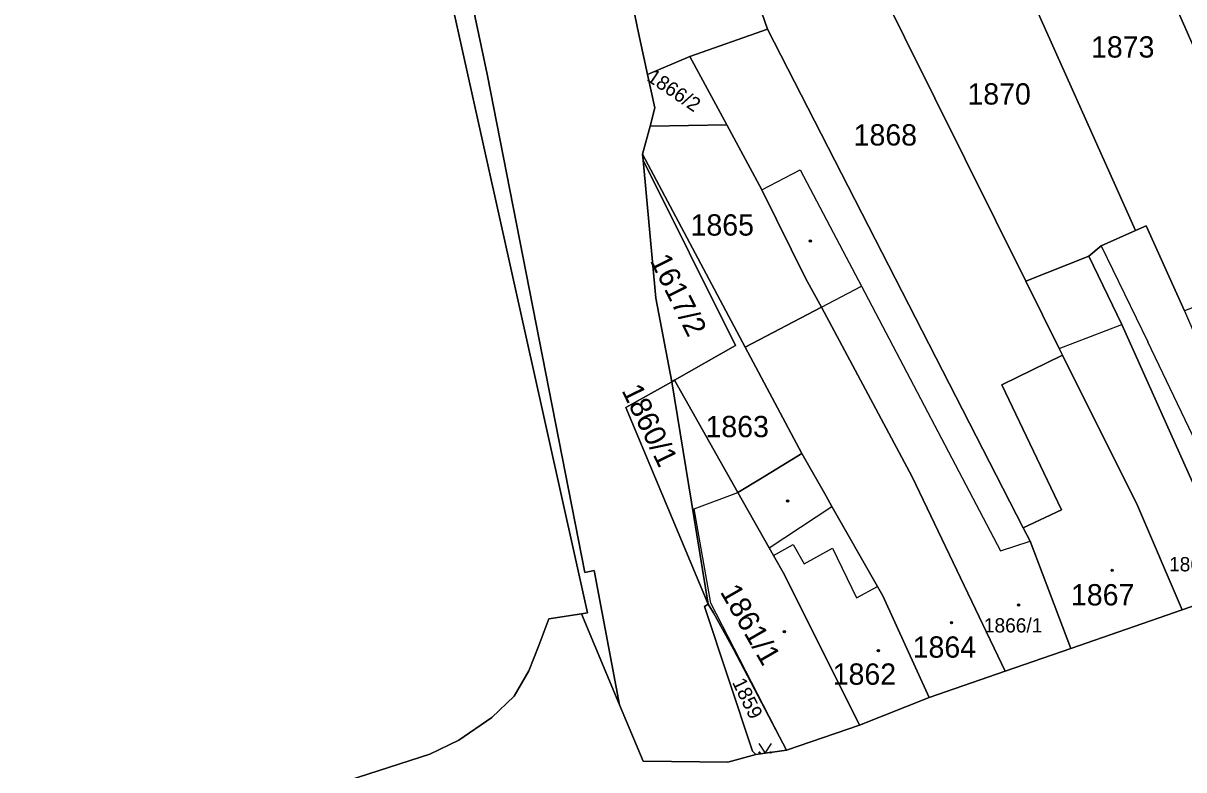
# Model space of a CAD drawing. Extents: x -596233 to -595156, y -1161235 to -1159375.
# Drawn here: x -595945.9 to -595853.3, y -1161150.2 to -1161090.6 of the extents above; entities that cross this region are included whole.
import ezdxf

# ---------------------------------------------------------------- set-up
doc = ezdxf.new("R2010")
doc.units = 0
for name, color, linetype in [('KN_CAR_KR', 7, 'Continuous'), ('KN_KULTURY', 7, 'Continuous'), ('KN_PARC_CIS_POZ', 7, 'Continuous'), ('KN_PARC_CIS_STAV', 7, 'Continuous'), ('KN_PARC_PLOCHA', 7, 'Continuous'), ('parcely_l', 7, 'Continuous')]:
    doc.layers.add(name, color=color, linetype=linetype)

msp = doc.modelspace()

# ---------------------------------------------------------------- linework, layer by layer
at = {"layer": 'KN_CAR_KR'}
for points in [[(-595886.97, -1161103.89), (-595883.91, -1161102.29)], [(-595883.91, -1161102.29), (-595880.24, -1161109.28)], [(-595859.88, -1161108.37), (-595856.16, -1161116.02)], [(-595880.24, -1161109.28), (-595879.02, -1161111.59)], [(-595882.21, -1161113.27), (-595879.02, -1161111.59)], [(-595879.02, -1161111.59), (-595867.93, -1161132.71)], [(-595863.23, -1161116.56), (-595858.25, -1161114.64)], [(-595851.12, -1161126.58), (-595856.16, -1161116.02)], [(-595892.35, -1161129.36), (-595888.87, -1161128.05)], [(-595891.04, -1161136.9), (-595892.35, -1161129.36)], [(-595886.37, -1161132.47), (-595881.37, -1161129.17)], [(-595886.03, -1161133.08), (-595884.47, -1161132.2)], [(-595884.47, -1161132.2), (-595883.59, -1161133.76)], [(-595883.59, -1161133.76), (-595881.33, -1161132.49)], [(-595881.33, -1161132.49), (-595879.4, -1161136.46)], [(-595867.93, -1161132.71), (-595865.56, -1161131.93)], [(-595879.4, -1161136.46), (-595877.74, -1161135.56)], [(-595884.99, -1161148.61), (-595891.04, -1161136.9)]]:
    msp.add_lwpolyline(points, dxfattribs=at)
at = {"layer": 'KN_KULTURY'}
msp.add_lwpolyline([(-595887.2018, -1161148.1016), (-595886.7018, -1161148.8516), (-595886.2018, -1161148.1016)], dxfattribs=at)
for centre, radius in [((-595883.1, -1161107.98), 0.09), ((-595883.1, -1161107.98), 0.0398), ((-595884.91, -1161128.73), 0.09), ((-595884.91, -1161128.73), 0.0398), ((-595859.01, -1161134.27), 0.09), ((-595859.01, -1161134.27), 0.0398), ((-595866.48, -1161137.03), 0.09), ((-595866.48, -1161137.03), 0.0398), ((-595885.16, -1161139.17), 0.09), ((-595885.16, -1161139.17), 0.0398), ((-595871.83, -1161138.45), 0.09), ((-595871.83, -1161138.45), 0.0398), ((-595877.66, -1161140.69), 0.09), ((-595877.66, -1161140.69), 0.0398), ((-595887.152, -1161148.8014), 0.05), ((-595886.2526, -1161148.8014), 0.05)]:
    msp.add_circle(centre, radius, dxfattribs=at)
at = {"layer": 'KN_PARC_PLOCHA'}
for points in [[(-595932.45, -1161008.33), (-595923.68, -1161035.97), (-595916.79, -1161060.49), (-595915.17, -1161066.86), (-595911.35, -1161082.95), (-595908.87, -1161094.65), (-595901.08, -1161134.44), (-595900.34, -1161134.29), (-595898.31, -1161145), (-595901.34, -1161137.73), (-595900.87, -1161137.65), (-595919, -1161056.06), (-595928.46, -1161024.22), (-595963.05, -1160926.68)], [(-595963.05, -1160926.68), (-595928.46, -1161024.22), (-595919, -1161056.06), (-595900.87, -1161137.65), (-595901.34, -1161137.73), (-595903.95, -1161138.15), (-595904.75, -1161140.26), (-595905.56, -1161142.28), (-595906.73, -1161144.3), (-595908.51, -1161146.01), (-595911.15, -1161147.82), (-595913.46, -1161148.94), (-595935.55, -1161156.06), (-595938.4, -1161156.98), (-595944.25, -1161155.13), (-595946.59, -1161152.37)], [(-595897.87, -1161086.16), (-595896.89, -1161090.99), (-595896.08, -1161094.7), (-595895.5, -1161097.34), (-595895.88, -1161098.81), (-595896.47, -1161101.05), (-595896.43, -1161101.54), (-595895.42, -1161112.55), (-595894.15, -1161119.21), (-595897.81, -1161121.28), (-595891.25, -1161136.97), (-595891.54, -1161137.15), (-595887.7, -1161148.71), (-595887.43, -1161148.97), (-595889.67, -1161149.57), (-595896.44, -1161149.51), (-595898.31, -1161145), (-595900.34, -1161134.29), (-595901.08, -1161134.44), (-595908.87, -1161094.65), (-595911.35, -1161082.95)], [(-595935.55, -1161156.06), (-595913.46, -1161148.94), (-595911.15, -1161147.82), (-595908.51, -1161146.01), (-595906.73, -1161144.3), (-595905.56, -1161142.28), (-595904.75, -1161140.26), (-595903.95, -1161138.15), (-595901.34, -1161137.73), (-595898.31, -1161145), (-595896.44, -1161149.51), (-595889.67, -1161149.57), (-595887.43, -1161148.97), (-595884.99, -1161148.61), (-595879.16, -1161146.62), (-595873.62, -1161144.41), (-595867.56, -1161142.31), (-595862.31, -1161140.5), (-595853.42, -1161137.42), (-595848.96, -1161135.89)]]:
    msp.add_lwpolyline(points, dxfattribs=at)
for points in [[(-595837.24, -1161088.2), (-595841.21, -1161090.03), (-595839.94, -1161093.17), (-595845.26, -1161095.8), (-595850.16, -1161097.83), (-595858.78, -1161078.24), (-595844.69, -1161072.03)], [(-595850.16, -1161097.83), (-595848.83, -1161100.85), (-595847.65, -1161103.46), (-595844.56, -1161110.24), (-595853.24, -1161113.55), (-595856.29, -1161106.76), (-595857.14, -1161107.14), (-595868.2, -1161082.4), (-595862.18, -1161079.61), (-595861.21, -1161079.27), (-595858.78, -1161078.24)], [(-595868.2, -1161082.4), (-595876.47, -1161086.05), (-595878, -1161086.81), (-595880.89, -1161088.44), (-595880.82, -1161089.01), (-595886.39, -1161089.71), (-595886.97, -1161089.77), (-595886.51, -1161091.06), (-595892.7, -1161093.24), (-595896.08, -1161094.7), (-595896.89, -1161090.99), (-595897.87, -1161086.16), (-595891.04, -1161084.75), (-595882.09, -1161083.33), (-595877.12, -1161082.53), (-595861.21, -1161079.27), (-595862.18, -1161079.61)], [(-595857.14, -1161107.14), (-595859.88, -1161108.37), (-595860.87, -1161109.2), (-595865.9, -1161111.18), (-595878, -1161086.81), (-595876.47, -1161086.05), (-595868.2, -1161082.4)], [(-595865.9, -1161111.18), (-595863.23, -1161116.56), (-595862.97, -1161117.08), (-595867.82, -1161119.46), (-595863.04, -1161129.43), (-595866.1, -1161130.88), (-595886.51, -1161091.06), (-595886.97, -1161089.77), (-595886.39, -1161089.71), (-595880.82, -1161089.01), (-595880.89, -1161088.44), (-595878, -1161086.81)], [(-595866.1, -1161130.88), (-595865.56, -1161131.93), (-595862.31, -1161140.5), (-595867.56, -1161142.31), (-595874.97, -1161126.8), (-595882.21, -1161113.27), (-595883.44, -1161110.99), (-595886.97, -1161103.89), (-595889.75, -1161098.72), (-595892.7, -1161093.24), (-595886.51, -1161091.06)], [(-595889.75, -1161098.72), (-595895.88, -1161098.81), (-595895.5, -1161097.34), (-595896.08, -1161094.7), (-595892.7, -1161093.24)], [(-595882.21, -1161113.27), (-595888.28, -1161116.45), (-595896.47, -1161101.05), (-595895.88, -1161098.81), (-595889.75, -1161098.72), (-595886.97, -1161103.89), (-595883.44, -1161110.99)], [(-595888.28, -1161116.45), (-595883.76, -1161124.94), (-595887.08, -1161126.96), (-595888.87, -1161128.05), (-595893.94, -1161119.09), (-595889.07, -1161116.33), (-595896.43, -1161101.54), (-595896.47, -1161101.05)], [(-595893.94, -1161119.09), (-595894.15, -1161119.21), (-595895.42, -1161112.55), (-595896.43, -1161101.54), (-595889.07, -1161116.33)], [(-595853.24, -1161113.55), (-595850.76, -1161119.29), (-595844.29, -1161134.3), (-595848.96, -1161135.89), (-595852.61, -1161127.22), (-595858.25, -1161114.64), (-595860.87, -1161109.2), (-595859.88, -1161108.37), (-595857.14, -1161107.14), (-595856.29, -1161106.76)], [(-595848.96, -1161135.89), (-595853.42, -1161137.42), (-595857, -1161129.1), (-595862.97, -1161117.08), (-595863.23, -1161116.56), (-595865.9, -1161111.18), (-595860.87, -1161109.2), (-595858.25, -1161114.64), (-595852.61, -1161127.22)], [(-595867.56, -1161142.31), (-595873.62, -1161144.41), (-595877.32, -1161136.3), (-595877.74, -1161135.56), (-595881.37, -1161129.17), (-595881.85, -1161128.29), (-595883.76, -1161124.94), (-595888.28, -1161116.45), (-595882.21, -1161113.27), (-595874.97, -1161126.8)], [(-595853.42, -1161137.42), (-595862.31, -1161140.5), (-595865.56, -1161131.93), (-595866.1, -1161130.88), (-595863.04, -1161129.43), (-595867.82, -1161119.46), (-595862.97, -1161117.08), (-595857, -1161129.1)], [(-595891.25, -1161136.97), (-595897.81, -1161121.28), (-595894.15, -1161119.21)], [(-595888.87, -1161128.05), (-595886.37, -1161132.47), (-595886.03, -1161133.08), (-595885.15, -1161134.64), (-595883.36, -1161138.21), (-595883.21, -1161138.52), (-595879.16, -1161146.62), (-595884.99, -1161148.61), (-595889.21, -1161140.56), (-595890.83, -1161137.66), (-595891.25, -1161136.97), (-595894.15, -1161119.21), (-595893.94, -1161119.09)], [(-595873.62, -1161144.41), (-595879.16, -1161146.62), (-595883.21, -1161138.52), (-595883.36, -1161138.21), (-595885.15, -1161134.64), (-595886.03, -1161133.08), (-595886.37, -1161132.47), (-595888.87, -1161128.05), (-595887.08, -1161126.96), (-595883.76, -1161124.94), (-595881.85, -1161128.29), (-595881.37, -1161129.17), (-595877.74, -1161135.56), (-595877.32, -1161136.3)], [(-595884.99, -1161148.61), (-595887.43, -1161148.97), (-595887.7, -1161148.71), (-595891.54, -1161137.15), (-595891.25, -1161136.97), (-595890.83, -1161137.66), (-595889.21, -1161140.56)]]:
    msp.add_lwpolyline(points, close=True, dxfattribs=at)
at = {"layer": 'parcely_l'}
for points in [[(-595970.85, -1160905.06), (-595963.05, -1160926.68), (-595928.46, -1161024.22), (-595919, -1161056.06), (-595900.87, -1161137.65), (-595901.34, -1161137.73)], [(-595898.31, -1161145), (-595900.34, -1161134.29), (-595901.08, -1161134.44), (-595908.87, -1161094.65), (-595911.35, -1161082.95), (-595915.17, -1161066.86), (-595916.79, -1161060.49), (-595923.68, -1161035.97), (-595932.45, -1161008.33), (-595931.85, -1161008.07), (-595933.08, -1161004.4), (-595933.76, -1161004.69), (-595934.5, -1161002.59), (-595933.82, -1161002.3), (-595934.86, -1160999.42), (-595935.6, -1160999.68), (-595936.32, -1160997.73), (-595935.57, -1160997.47), (-595936.57, -1160994.57), (-595937.32, -1160994.82), (-595945.84, -1160970.67), (-595945.16, -1160970.37), (-595946.16, -1160967.59)], [(-595858.78, -1161078.24), (-595850.16, -1161097.83)], [(-595868.2, -1161082.4), (-595857.14, -1161107.14)], [(-595897.87, -1161086.16), (-595896.89, -1161090.99), (-595896.08, -1161094.7)], [(-595878, -1161086.81), (-595880.89, -1161088.44), (-595880.82, -1161089.01), (-595886.39, -1161089.71), (-595886.97, -1161089.77), (-595886.51, -1161091.06)], [(-595865.9, -1161111.18), (-595878, -1161086.81)], [(-595886.51, -1161091.06), (-595892.7, -1161093.24)], [(-595866.1, -1161130.88), (-595886.51, -1161091.06)], [(-595892.7, -1161093.24), (-595896.08, -1161094.7)], [(-595889.75, -1161098.72), (-595892.7, -1161093.24)], [(-595896.08, -1161094.7), (-595895.5, -1161097.34), (-595895.88, -1161098.81)], [(-595895.88, -1161098.81), (-595896.47, -1161101.05)], [(-595895.88, -1161098.81), (-595889.75, -1161098.72)], [(-595889.75, -1161098.72), (-595886.97, -1161103.89), (-595883.44, -1161110.99), (-595882.21, -1161113.27)], [(-595896.43, -1161101.54), (-595896.47, -1161101.05)], [(-595896.47, -1161101.05), (-595888.28, -1161116.45)], [(-595893.94, -1161119.09), (-595889.07, -1161116.33), (-595896.43, -1161101.54)], [(-595896.43, -1161101.54), (-595895.42, -1161112.55), (-595894.15, -1161119.21)], [(-595857.14, -1161107.14), (-595856.29, -1161106.76), (-595853.24, -1161113.55)], [(-595860.87, -1161109.2), (-595859.88, -1161108.37), (-595857.14, -1161107.14)], [(-595865.9, -1161111.18), (-595860.87, -1161109.2)], [(-595860.87, -1161109.2), (-595858.25, -1161114.64), (-595852.61, -1161127.22), (-595848.96, -1161135.89)], [(-595862.97, -1161117.08), (-595863.23, -1161116.56), (-595865.9, -1161111.18)], [(-595888.28, -1161116.45), (-595882.21, -1161113.27)], [(-595882.21, -1161113.27), (-595874.97, -1161126.8), (-595867.56, -1161142.31)], [(-595888.28, -1161116.45), (-595883.76, -1161124.94)], [(-595862.97, -1161117.08), (-595867.82, -1161119.46), (-595863.04, -1161129.43), (-595866.1, -1161130.88)], [(-595853.42, -1161137.42), (-595857, -1161129.1), (-595862.97, -1161117.08)], [(-595894.15, -1161119.21), (-595897.81, -1161121.28), (-595891.25, -1161136.97)], [(-595894.15, -1161119.21), (-595893.94, -1161119.09)], [(-595891.25, -1161136.97), (-595894.15, -1161119.21)], [(-595888.87, -1161128.05), (-595893.94, -1161119.09)], [(-595883.76, -1161124.94), (-595887.08, -1161126.96), (-595888.87, -1161128.05)], [(-595873.62, -1161144.41), (-595877.32, -1161136.3), (-595877.74, -1161135.56), (-595881.37, -1161129.17), (-595881.85, -1161128.29), (-595883.76, -1161124.94)], [(-595888.87, -1161128.05), (-595886.37, -1161132.47), (-595886.03, -1161133.08), (-595885.15, -1161134.64), (-595883.36, -1161138.21), (-595883.21, -1161138.52), (-595879.16, -1161146.62)], [(-595862.31, -1161140.5), (-595865.56, -1161131.93), (-595866.1, -1161130.88)], [(-595848.96, -1161135.89), (-595853.42, -1161137.42)], [(-595891.25, -1161136.97), (-595891.54, -1161137.15), (-595887.7, -1161148.71), (-595887.43, -1161148.97)], [(-595891.25, -1161136.97), (-595890.83, -1161137.66), (-595889.21, -1161140.56), (-595884.99, -1161148.61)], [(-595938.4, -1161156.98), (-595935.55, -1161156.06), (-595913.46, -1161148.94), (-595911.15, -1161147.82), (-595908.51, -1161146.01), (-595906.73, -1161144.3), (-595905.56, -1161142.28), (-595904.75, -1161140.26), (-595903.95, -1161138.15), (-595901.34, -1161137.73)], [(-595901.34, -1161137.73), (-595898.31, -1161145)], [(-595862.31, -1161140.5), (-595853.42, -1161137.42)], [(-595867.56, -1161142.31), (-595862.31, -1161140.5)], [(-595873.62, -1161144.41), (-595867.56, -1161142.31)], [(-595879.16, -1161146.62), (-595873.62, -1161144.41)], [(-595887.43, -1161148.97), (-595889.67, -1161149.57), (-595896.44, -1161149.51), (-595898.31, -1161145)], [(-595884.99, -1161148.61), (-595879.16, -1161146.62)], [(-595887.43, -1161148.97), (-595884.99, -1161148.61)]]:
    msp.add_lwpolyline(points, dxfattribs=at)

# ---------------------------------------------------------------- texts
at = {"layer": 'KN_PARC_CIS_POZ'}
for s, p in [('1873', (-595860.6966, -1161093.34)), ('1870', (-595870.5566, -1161097.09)), ('1868', (-595879.6366, -1161100.36)), ('1865', (-595892.6466, -1161107.55)), ('1863', (-595891.4566, -1161123.64))]:
    msp.add_text(s, height=1.7, dxfattribs=at).set_placement(p)
for s, height, rotation, p in [('1866/2', 1.14, 325.953087, (-595896.2163, -1161095.1216)), ('1617/2', 1.7, 296.524858, (-595895.921, -1161109.5304)), ('1860/1', 1.7, 295.959115, (-595898.1784, -1161119.9093)), ('1859', 1.14, 296.137982, (-595889.3607, -1161143.2038))]:
    msp.add_text(s, height=height, rotation=rotation, dxfattribs=at).set_placement(p)
at = {"layer": 'KN_PARC_CIS_STAV'}
for s, height, p in [('1869', 1.14, (-595854.47, -1161134.35)), ('1867', 1.7, (-595862.2966, -1161137.07)), ('1866/1', 1.14, (-595869.245, -1161139.23)), ('1864', 1.7, (-595874.9266, -1161141.24)), ('1862', 1.7, (-595881.3066, -1161143.4))]:
    msp.add_text(s, height=height, dxfattribs=at).set_placement(p)
msp.add_text('1861/1', height=1.7, rotation=299.999765, dxfattribs=at).set_placement((-595890.3308, -1161135.9851))

doc.saveas('drawing.dxf')
